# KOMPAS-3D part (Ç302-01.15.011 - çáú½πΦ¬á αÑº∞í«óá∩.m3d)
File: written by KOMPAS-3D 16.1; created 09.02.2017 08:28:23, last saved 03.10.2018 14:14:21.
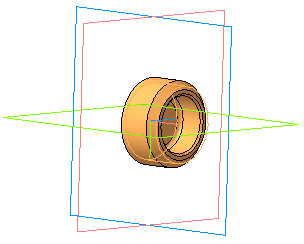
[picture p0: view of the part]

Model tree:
1. Эскиз:7
2. Операция вращения:1
     Угол 1 = 360
3. Скругление:17
     Радиус = 1
4. Условное изображение резьбы:1
     Длина резьбы = 10; Шаг резьбы = 1.814; Номинальный диаметр резьбы = 20.955
5. Подгонка:1
6. Фаска:1
     Угол = 45; Длина 1 = 2; Длина 2 = 2
7. Фаска:2
     Угол = 45; Длина 1 = 0.5; Длина 2 = 0.5
8. Эскиз:9
9. Операция выдавливания:1
     Расстояние 1 = 4
10. Эскиз:10
11. Вырезать элемент выдавливания:1
     Расстояние 1 = 4
12. Сечение поверхностью:1  (labels: А302-01.15.011)

Expressions: G 1/2
Referenced files in C:\Program Files\ASCON\KOMPAS-3D V16\Sys\Thread\: cil2_6357-81.xml
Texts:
  Линейный размер с обрывом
